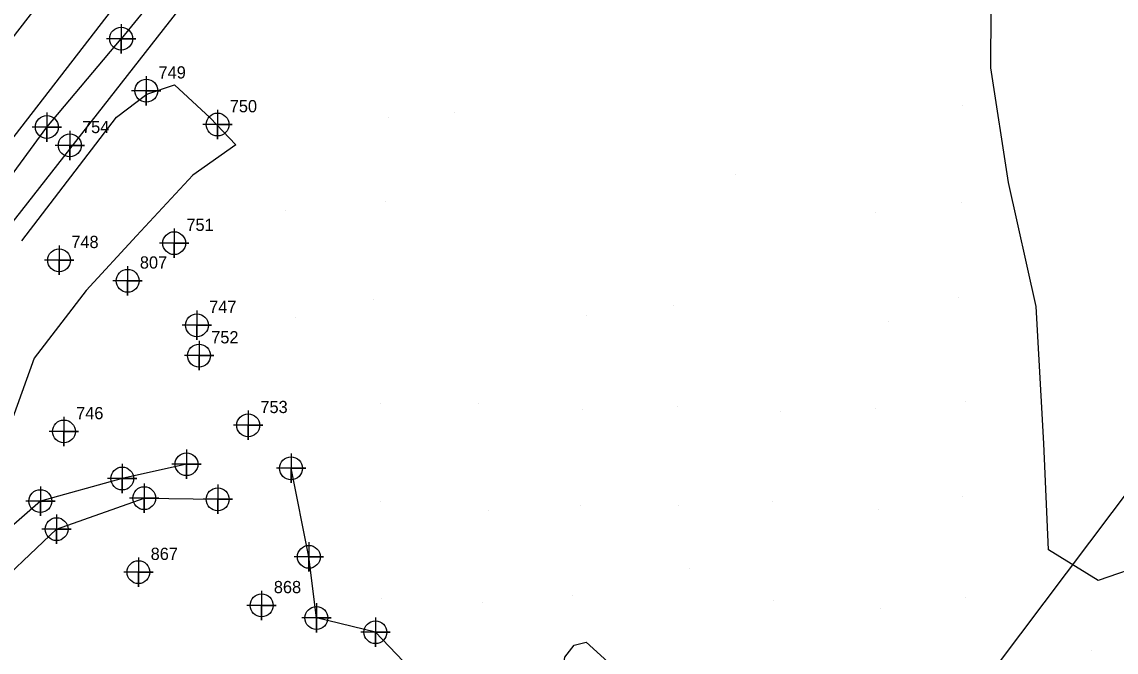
# Model space of a CAD drawing. Extents: x 1497074 to 1501343, y 481943 to 486114.
# Drawn here: x 1498929.9 to 1499153.8, y 485116.2 to 485245.1 of the extents above; entities that cross this region are included whole.
import ezdxf

# ---------------------------------------------------------------- set-up
doc = ezdxf.new("R2010")
doc.units = 0
for name, color, linetype in [('Exist DTM Breakline', 7, 'Continuous'), ('Exist DTM Breakline Cogo Point CELL', 7, 'Continuous'), ('Exist DTM Crownline', 7, 'Continuous'), ('Exist DTM Regular Point CELL', 7, 'Continuous'), ('Exist DTM Regular Point Cogo Number', 7, 'Continuous'), ('Exist Roads EOP', 7, 'Continuous'), ('PH Exist DTM Boundary', 7, 'Continuous'), ('PH Exist DTM Breakline', 7, 'Continuous'), ('PH Exist DTM Obscure Area', 7, 'Continuous'), ('PH Exist DTM Point', 7, 'Continuous')]:
    doc.layers.add(name, color=color, linetype=linetype)

msp = doc.modelspace()

# ---------------------------------------------------------------- linework, layer by layer
at = {"layer": 'Exist DTM Breakline'}
for points in [[(1498805.95, 485054.25), (1498833.45, 485089.98), (1498860.79, 485126.09), (1498887.46, 485159.9), (1498914.16, 485195.14), (1498935.01, 485223.58), (1498950.21, 485241.65)], [(1498963.58, 485154.61), (1498950.43, 485151.68), (1498933.68, 485147.06), (1498922.77, 485137.59), (1498906.95, 485114.19), (1498898.82, 485097.51), (1498890.98, 485070.05), (1498884.07, 485050.09), (1498876.91, 485030.97), (1498872.08, 485011.19)], [(1499017.74, 485098.64), (1499013.59, 485108.36), (1499002.23, 485120.24), (1498990.16, 485123.16), (1498988.61, 485135.66), (1498984.96, 485153.78)], [(1498891.9, 484978.31), (1498889.24, 485025.19), (1498896.9, 485043.7), (1498902.05, 485073.4), (1498909.09, 485094.11), (1498914.43, 485114.93), (1498921.86, 485126.97), (1498937, 485141.32), (1498954.93, 485147.67), (1498969.97, 485147.43)]]:
    msp.add_lwpolyline(points, dxfattribs=at)
at = {"layer": 'Exist DTM Breakline Cogo Point CELL'}
for points in [[(1498950.21, 485244.65), (1498950.21, 485238.65), (1498950.21, 485241.65), (1498953.21, 485241.65), (1498947.21, 485241.65)], [(1498935.01, 485226.58), (1498935.01, 485220.58), (1498935.01, 485223.58), (1498938.01, 485223.58), (1498932.01, 485223.58)], [(1498963.58, 485157.61), (1498963.58, 485151.61), (1498963.58, 485154.61), (1498966.58, 485154.61), (1498960.58, 485154.61)], [(1498984.96, 485156.78), (1498984.96, 485150.78), (1498984.96, 485153.78), (1498987.96, 485153.78), (1498981.96, 485153.78)], [(1498950.43, 485154.68), (1498950.43, 485148.68), (1498950.43, 485151.68), (1498953.43, 485151.68), (1498947.43, 485151.68)], [(1498933.68, 485150.06), (1498933.68, 485144.06), (1498933.68, 485147.06), (1498936.68, 485147.06), (1498930.68, 485147.06)], [(1498954.93, 485150.67), (1498954.93, 485144.67), (1498954.93, 485147.67), (1498957.93, 485147.67), (1498951.93, 485147.67)], [(1498969.97, 485150.43), (1498969.97, 485144.43), (1498969.97, 485147.43), (1498972.97, 485147.43), (1498966.97, 485147.43)], [(1498937, 485144.32), (1498937, 485138.32), (1498937, 485141.32), (1498940, 485141.32), (1498934, 485141.32)], [(1498988.61, 485138.66), (1498988.61, 485132.66), (1498988.61, 485135.66), (1498991.61, 485135.66), (1498985.61, 485135.66)], [(1498990.16, 485126.16), (1498990.16, 485120.16), (1498990.16, 485123.16), (1498993.16, 485123.16), (1498987.16, 485123.16)], [(1499002.23, 485123.24), (1499002.23, 485117.24), (1499002.23, 485120.24), (1499005.23, 485120.24), (1498999.23, 485120.24)]]:
    msp.add_lwpolyline(points, dxfattribs=at)
for centre in [(1498950.21, 485241.65), (1498935.01, 485223.58), (1498963.58, 485154.61), (1498984.96, 485153.78), (1498950.43, 485151.68), (1498933.68, 485147.06), (1498954.93, 485147.67), (1498969.97, 485147.43), (1498937, 485141.32), (1498988.61, 485135.66), (1498990.16, 485123.16), (1499002.23, 485120.24)]:
    msp.add_circle(centre, 2.34, dxfattribs=at)
at = {"layer": 'Exist DTM Crownline'}
msp.add_lwpolyline([(1498753.92, 485018.83), (1498767.97, 485036.35), (1498784.41, 485057.61), (1498813.33, 485094.71), (1498845.11, 485135.39), (1498876.05, 485175.22), (1498907.7, 485215.72), (1498939.87, 485257.15), (1498970.73, 485296.32), (1499001.6, 485335.5), (1499032.55, 485374.36), (1499053.88, 485400.5), (1499073.91, 485423.48), (1499090.49, 485441.64), (1499112.37, 485464.57), (1499148.43, 485501.47), (1499184.54, 485537.77), (1499215.93, 485569.25), (1499248.51, 485602.52), (1499285.02, 485638.96), (1499320.99, 485674.8), (1499344.91, 485698.57), (1499374.04, 485727.35), (1499398.21, 485750.96)], dxfattribs=at)
at = {"layer": 'Exist DTM Regular Point CELL'}
for points in [[(1498955.36, 485234.01), (1498955.36, 485228.01), (1498955.36, 485231.01), (1498958.36, 485231.01), (1498952.36, 485231.01)], [(1498969.93, 485227.1), (1498969.93, 485221.1), (1498969.93, 485224.1), (1498972.93, 485224.1), (1498966.93, 485224.1)], [(1498939.71, 485222.84), (1498939.71, 485216.84), (1498939.71, 485219.84), (1498942.71, 485219.84), (1498936.71, 485219.84)], [(1498961.06, 485202.83), (1498961.06, 485196.83), (1498961.06, 485199.83), (1498964.06, 485199.83), (1498958.06, 485199.83)], [(1498937.52, 485199.33), (1498937.52, 485193.33), (1498937.52, 485196.33), (1498940.52, 485196.33), (1498934.52, 485196.33)], [(1498951.54, 485195.13), (1498951.54, 485189.13), (1498951.54, 485192.13), (1498954.54, 485192.13), (1498948.54, 485192.13)], [(1498965.71, 485186.04), (1498965.71, 485180.04), (1498965.71, 485183.04), (1498968.71, 485183.04), (1498962.71, 485183.04)], [(1498966.14, 485179.83), (1498966.14, 485173.83), (1498966.14, 485176.83), (1498969.14, 485176.83), (1498963.14, 485176.83)], [(1498976.2, 485165.57), (1498976.2, 485159.57), (1498976.2, 485162.57), (1498979.2, 485162.57), (1498973.2, 485162.57)], [(1498938.5, 485164.31), (1498938.5, 485158.31), (1498938.5, 485161.31), (1498941.5, 485161.31), (1498935.5, 485161.31)], [(1498953.75, 485135.53), (1498953.75, 485129.53), (1498953.75, 485132.53), (1498956.75, 485132.53), (1498950.75, 485132.53)], [(1498978.95, 485128.73), (1498978.95, 485122.73), (1498978.95, 485125.73), (1498981.95, 485125.73), (1498975.95, 485125.73)]]:
    msp.add_lwpolyline(points, dxfattribs=at)
for centre in [(1498955.36, 485231.01), (1498969.93, 485224.1), (1498939.71, 485219.84), (1498961.06, 485199.83), (1498937.52, 485196.33), (1498951.54, 485192.13), (1498965.71, 485183.04), (1498966.14, 485176.83), (1498976.2, 485162.57), (1498938.5, 485161.31), (1498953.75, 485132.53), (1498978.95, 485125.73)]:
    msp.add_circle(centre, 2.34, dxfattribs=at)
at = {"layer": 'Exist Roads EOP'}
msp.add_lwpolyline([(1499157.4, 485492.59), (1499121.26, 485455.44), (1499103.51, 485436.37), (1499090.83, 485422.86), (1499076.19, 485406.52), (1499058.81, 485386.53), (1499043.51, 485368.33), (1499011.4, 485327.87), (1498980.6, 485289.07), (1498949.57, 485249.28), (1498917.76, 485208.17), (1498886.39, 485167.84), (1498854.95, 485127.37), (1498823.54, 485086.98), (1498794.25, 485049.83), (1498777.79, 485028.94), (1498763.43, 485011.14)], dxfattribs=at)
at = {"layer": 'PH Exist DTM Boundary'}
msp.add_lwpolyline([(1498924.23, 484841.06), (1498545.19, 485168.9), (1498846.5, 485569.16), (1499227.59, 485244.03)], close=True, dxfattribs=at)
at = {"layer": 'PH Exist DTM Breakline'}
for points in [[(1499014.39, 485317.8), (1498993.82, 485290.71), (1498966.9, 485253.95), (1498921.62, 485196.13)], [(1499006.18, 485313.63), (1498991.2, 485293.86), (1498972.62, 485269.2), (1498950.21, 485241.65)], [(1499037.83, 485105.16), (1499040.94, 485107.91), (1499040.55, 485111.94), (1499041, 485115.16), (1499042.88, 485117.61), (1499045.35, 485118.18), (1499049.03, 485114.84), (1499054.89, 485109.41), (1499058.26, 485104.57), (1499059.74, 485099.51), (1499061.08, 485094.59), (1499061.3, 485091.46), (1499059.68, 485088.23), (1499057.08, 485085.42), (1499054.3, 485082.41), (1499050.52, 485078.33), (1499047.14, 485074.67), (1499043.55, 485070.79), (1499040.79, 485067.83), (1499038.24, 485065.07), (1499037.17, 485061.55), (1499037.99, 485057.71), (1499038.23, 485054.01), (1499038.16, 485050.44)]]:
    msp.add_lwpolyline(points, dxfattribs=at)
at = {"layer": 'PH Exist DTM Obscure Area'}
for points in [[(1499174.34, 485137.93), (1499160.4, 485134.34), (1499150.09, 485130.83), (1499139.94, 485137.08), (1499138.98, 485158.83), (1499137.42, 485186.87), (1499131.76, 485212.27), (1499128.15, 485235.71), (1499128.29, 485259.69), (1499129.56, 485280.15), (1499132.29, 485298.2), (1499132.53, 485317.27), (1499132.06, 485333.2)], [(1498929.86, 485200.31), (1498949.24, 485225.58), (1498955.47, 485230.34), (1498961.15, 485232.22), (1498968.44, 485225.48), (1498973.7, 485219.95), (1498964.85, 485213.74)], [(1498964.85, 485213.74), (1498953.36, 485201.31), (1498943.05, 485190.16), (1498932.39, 485176.27), (1498927.4, 485162.25)]]:
    msp.add_lwpolyline(points, dxfattribs=at)
at = {"layer": 'PH Exist DTM Point'}
for p, q in [((1499122.36, 485227.95), (1499122.36, 485227.95)), ((1499004.9, 485225.59), (1499004.9, 485225.59)), ((1499018.43, 485226.48), (1499018.43, 485226.48)), ((1499075.96, 485213.86), (1499075.96, 485213.86)), ((1499004.34, 485208.33), (1499004.34, 485208.33)), ((1499122.17, 485208.12), (1499122.17, 485208.12)), ((1498983.88, 485206.53), (1498983.88, 485206.53)), ((1499104.54, 485206.05), (1499104.54, 485206.05)), ((1499001.89, 485188.38), (1499001.89, 485188.38)), ((1499063.3, 485187.07), (1499063.3, 485187.07)), ((1499121.6, 485188.64), (1499121.6, 485188.64)), ((1498985.93, 485184.64), (1498985.93, 485184.64)), ((1499045.41, 485185.12), (1499045.41, 485185.12)), ((1499107.27, 485183.8), (1499107.27, 485183.8)), ((1499003.3, 485167.07), (1499003.3, 485167.07)), ((1499023.3, 485167.07), (1499023.3, 485167.07)), ((1499122.91, 485167.44), (1499122.91, 485167.44)), ((1498984.57, 485165.9), (1498984.57, 485165.9)), ((1499044.59, 485165.88), (1499044.59, 485165.88)), ((1499063.94, 485166.48), (1499063.94, 485166.48)), ((1499085.14, 485165.37), (1499085.14, 485165.37)), ((1499104.47, 485165.99), (1499104.47, 485165.99)), ((1499003.3, 485147.07), (1499003.3, 485147.07)), ((1499083.47, 485146.92), (1499083.47, 485146.92)), ((1499122.3, 485148), (1499122.3, 485148)), ((1499025.28, 485145.24), (1499025.28, 485145.24)), ((1499044.22, 485146.22), (1499044.22, 485146.22)), ((1499064.25, 485146.2), (1499064.25, 485146.2)), ((1499105.1, 485145.41), (1499105.1, 485145.41)), ((1499066.45, 485133.22), (1499066.45, 485133.22)), ((1499003.42, 485127.23), (1499003.42, 485127.23)), ((1499042.61, 485127.71), (1499042.61, 485127.71)), ((1499083.57, 485126.82), (1499083.57, 485126.82)), ((1499122.92, 485127.43), (1499122.92, 485127.43)), ((1499024.1, 485126.33), (1499024.1, 485126.33)), ((1499105.51, 485125.03), (1499105.51, 485125.03)), ((1499148.68, 485116.48), (1499148.68, 485116.48))]:
    msp.add_line(p, q, dxfattribs=at)

# ---------------------------------------------------------------- texts
at = {"layer": 'Exist DTM Regular Point Cogo Number'}
for s, p in [('749', (1498957.86, 485233.51)), ('750', (1498972.43, 485226.6)), ('754', (1498942.21, 485222.34)), ('751', (1498963.56, 485202.33)), ('748', (1498940.02, 485198.83)), ('807', (1498954.04, 485194.63)), ('747', (1498968.21, 485185.54)), ('752', (1498968.64, 485179.33)), ('753', (1498978.7, 485165.07)), ('746', (1498941, 485163.81)), ('867', (1498956.25, 485135.03)), ('868', (1498981.45, 485128.23))]:
    msp.add_text(s, height=2.5, dxfattribs=at).set_placement(p)

doc.saveas('drawing.dxf')
